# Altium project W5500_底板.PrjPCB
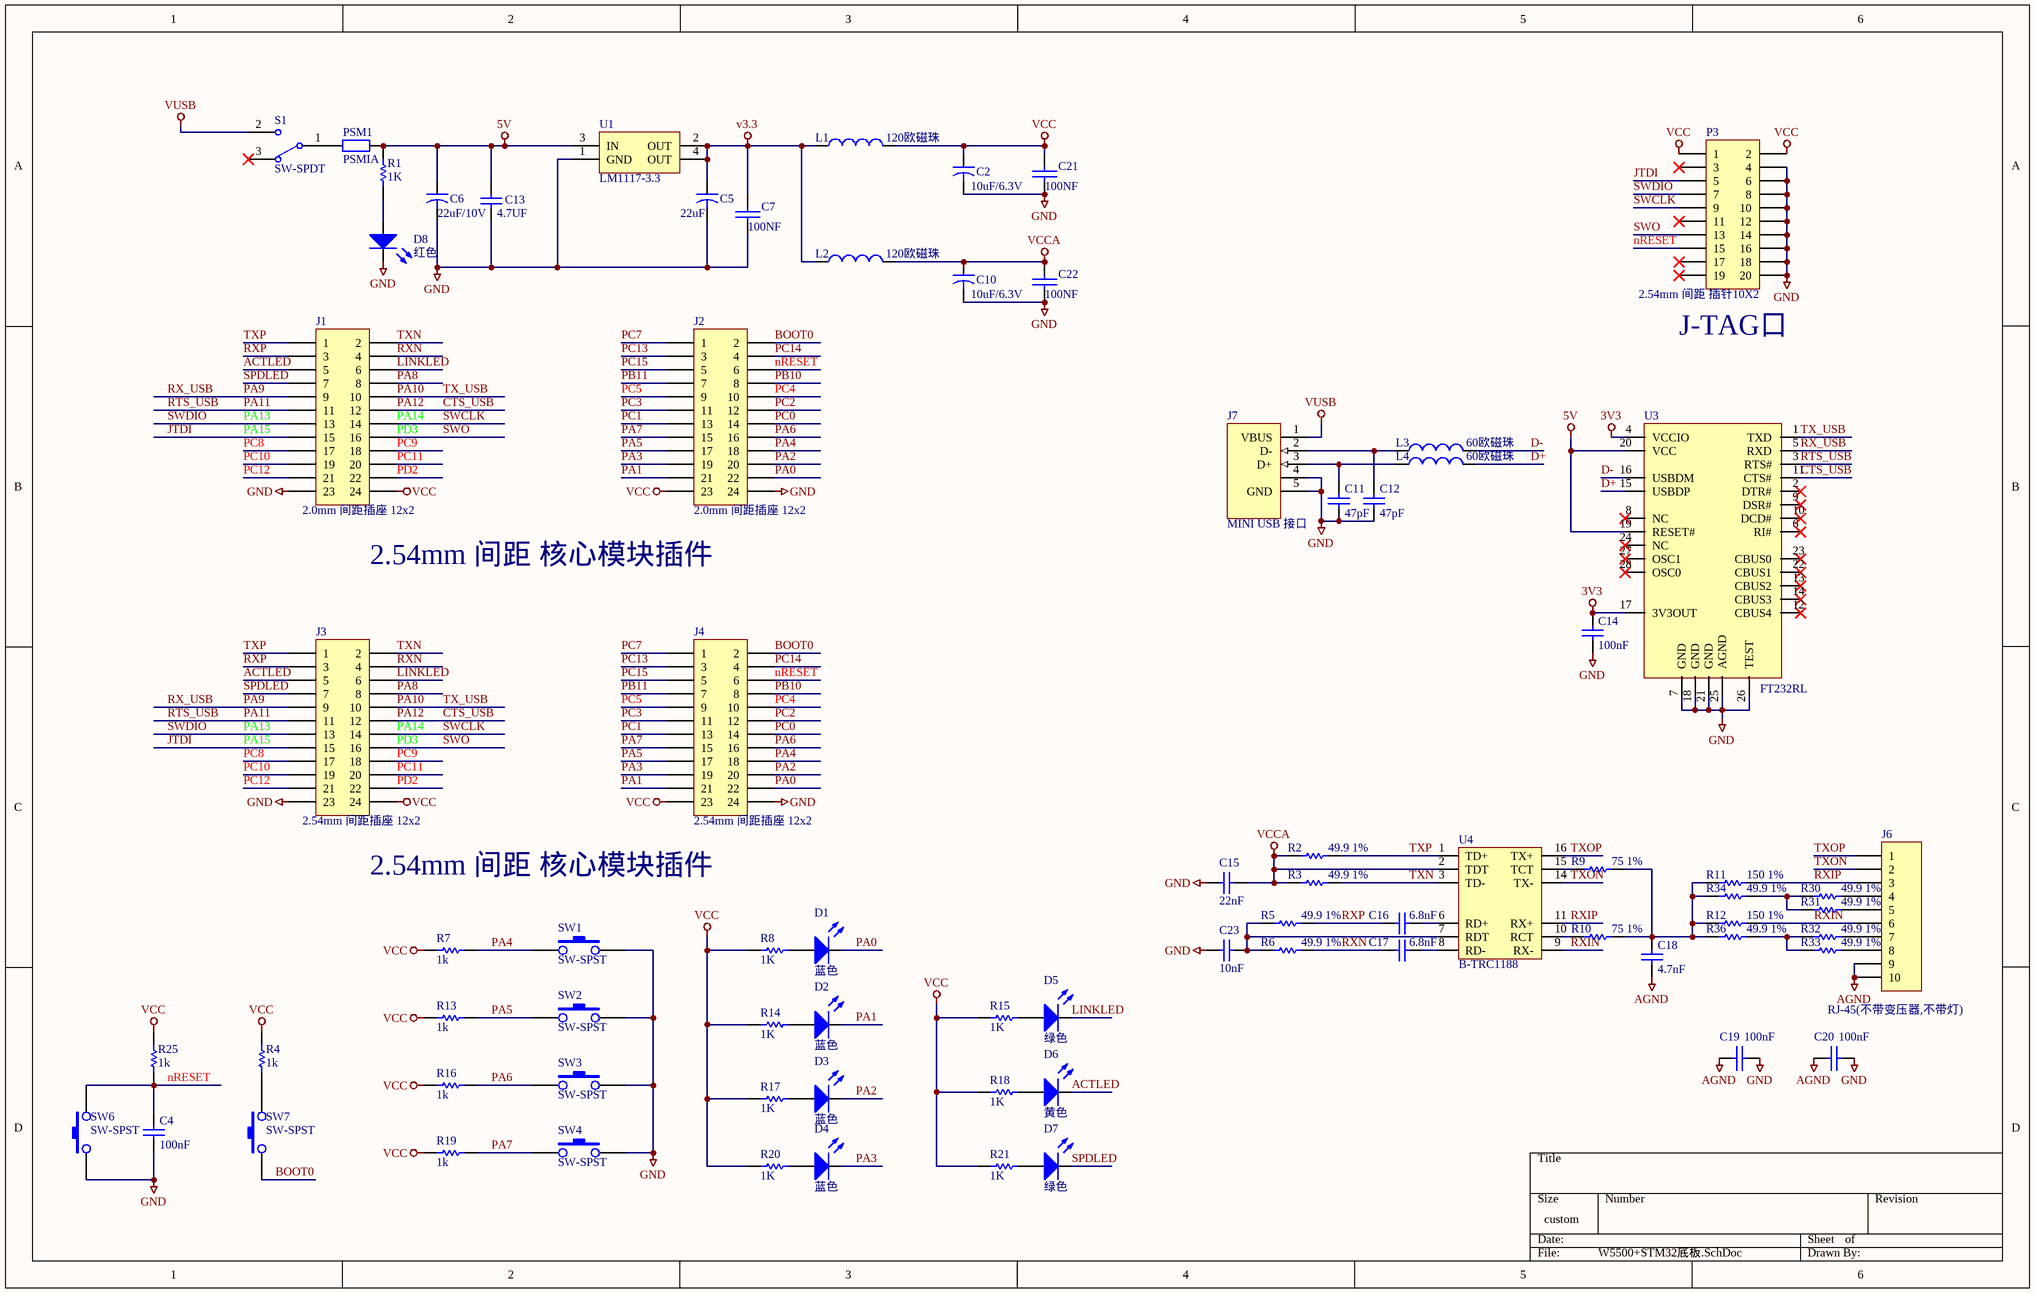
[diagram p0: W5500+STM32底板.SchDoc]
1 sheet, 77 parts. Net scope: global (net labels, ports and power ports of the same name join across sheets).
Board file: W5500_底板.PcbDoc

## Sheet W5500+STM32底板.SchDoc
size 381 x 241 mm

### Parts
C2  value 10uF/6.3V  [CR1206]  (hidden comment: Cap2)
C4  value 100nF  [CR0603]  (hidden comment: Cap)
C5  value 22uF  [CR1206]  (hidden comment: Cap2)
C6  value 22uF/10V  [cr1206]  (hidden comment: Cap2)
C7  value 100NF  [CR0603]  (hidden comment: 104)
C10  value 10uF/6.3V  [CR1206]  (hidden comment: Cap2)
C11  value 47pF  [CR0603]  (hidden comment: Cap)
C12  value 47pF  [CR0603]  (hidden comment: Cap)
C13  value 4.7UF  [CR0805]  (hidden comment: Cap)
C14  value 100nF  [CR0603]  (hidden comment: Cap)
C15  value 22nF  [CR0603]  (hidden comment: Cap)
C16  value 6.8nF  [CR0603]  (hidden comment: Cap)
C17  value 6.8nF  [CR0603]  (hidden comment: Cap)
C18  value 4.7nF  [CR0603]  (hidden comment: Cap)
C19  100nF  [CR0603]
C20  100nF  [CR0603]
C21  value 100NF  [CR0603]  (hidden comment: 104)
C22  value 100NF  [CR0603]  (hidden comment: 104)
C23  value 10nF  [CR0603]  (hidden comment: Cap)
D1  蓝色  [CR0603 发光二极管]
D2  蓝色  [CR0603 发光二极管]
D3  蓝色  [CR0603 发光二极管]
D4  蓝色  [CR0603 发光二极管]
D5  绿色  [CR0603 发光二极管]
D6  黄色  [CR0603 发光二极管]
D7  绿色  [CR0603 发光二极管]
D8  红色  [CR0603 发光二极管]
J1  2.0mm 间距插座 12x2  [HDR2X12]
J2  2.0mm 间距插座 12x2  [HDR2X12]
J3  2.54mm 间距插座 12x2  [HDR2X12]
J4  2.54mm 间距插座 12x2  [HDR2X12]
J6  RJ-45(不带变压器,不带灯)  [RJ-45(SC902-5921S)]
J7  MINI USB 接口  [440479]
L1  value 120欧磁珠  [cr0603]  (hidden comment: Inductor)
L2  value 120欧磁珠  [cr0603]  (hidden comment: Inductor)
L3  value 60欧磁珠  [cr0603]  (hidden comment: Inductor)
L4  value 60欧磁珠  [cr0603]  (hidden comment: Inductor)
P3  2.54mm 间距 插针10X2  [HDR2X10]
PSM1  PSMIA  [保险管？]
R1  value 1K  [CR0603]  (hidden comment: Res1)
R2  value 49.9 1%  [CR0603]  (hidden comment: Res1)
R3  value 49.9 1%  [CR0603]  (hidden comment: Res1)
R4  value 1k  [CR0603]  (hidden comment: Res1)
R5  value 49.9 1%  [CR0603]  (hidden comment: Res1)
R6  value 49.9 1%  [CR0603]  (hidden comment: Res1)
R7  value 1k  [CR0603]  (hidden comment: Res1)
R8  value 1K  [CR0603]  (hidden comment: Res1)
R9  value 75 1%  [CR0603]  (hidden comment: Res1)
R10  value 75 1%  [CR0603]  (hidden comment: Res1)
R11  value 150 1%  [CR0603]  (hidden comment: Res1)
R12  value 150 1%  [CR0603]  (hidden comment: Res1)
R13  value 1k  [CR0603]  (hidden comment: Res1)
R14  value 1K  [CR0603]  (hidden comment: Res1)
R15  value 1K  [CR0603]  (hidden comment: Res1)
R16  value 1k  [CR0603]  (hidden comment: Res1)
R17  value 1K  [CR0603]  (hidden comment: Res1)
R18  value 1K  [CR0603]  (hidden comment: Res1)
R19  value 1k  [CR0603]  (hidden comment: Res1)
R20  value 1K  [CR0603]  (hidden comment: Res1)
R21  value 1K  [CR0603]  (hidden comment: Res1)
R25  value 1k  [CR0603]  (hidden comment: Res1)
R30  value 49.9 1%  [CR0603]  (hidden comment: Res1)
R31  value 49.9 1%  [CR0603]  (hidden comment: Res1)
R32  value 49.9 1%  [CR0603]  (hidden comment: Res1)
R33  value 49.9 1%  [CR0603]  (hidden comment: Res1)
R34  value 49.9 1%  [CR0603]  (hidden comment: Res1)
R36  value 49.9 1%  [CR0603]  (hidden comment: Res1)
S1  SW-SPDT  [单刀双路拨码]
SW1  SW-SPST  [直插上位按键]
SW2  SW-SPST  [直插上位按键]
SW3  SW-SPST  [直插上位按键]
SW4  SW-SPST  [直插上位按键]
SW6  SW-SPST  [直插上位按键]
SW7  SW-SPST  [直插上位按键]
U1  LM1117-3.3  [SOT-223]
U3  FT232RL  [SSOP28]
U4  B-TRC1188  [11FB-05NL]

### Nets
3V3: C14.2 U3.4(VCCIO) U3.17(3V3OUT)
5V: C6.1 C13.2 PSM1.2 R1.1 U1.3(IN) U3.19(RESET#) U3.20(VCC)
AGND: C18.1 C19.1 C20.1 J6.9 J6.10
GND: C2.2 C4.1 C5.2 C6.2 C7.2 C10.2 C11.1 C12.1 C13.1 C14.1 C15.2 C19.2 C20.2 C21.2 C22.2 C23.1 D8.2(K) J1.23 J2.24 J3.23 J4.24 J7.4 J7.5(GND) J7.6(SHLD) J7.7(SHLD) J7.8(SHLD) J7.9(SHLD) P3.4 P3.6 P3.8 P3.10 P3.12 P3.14 P3.16 P3.18 P3.20 SW1.3 SW2.3 SW3.3 SW4.3 SW6.3 U1.1(GND) U3.7(GND) U3.18(GND) U3.21(GND) U3.25(AGND) U3.26(TEST)
v3.3: C5.1 C7.1 L1.1 L2.1 U1.2(OUT) U1.4(OUT)
VCC: C2.1 C21.1 J1.24 J2.23 J3.24 J4.23 L1.2 P3.1 P3.2 R4.1 R7.1 R8.1 R13.1 R14.1 R15.1 R16.1 R17.1 R18.1 R19.1 R20.1 R21.1 R25.1
VCCA: C10.1 C15.1 C22.1 L2.2 R2.2 R3.2 U4.2(TDT)
VUSB: J7.1(VBUS) S1.2
ACTLED: D6.2(K) J1.5 J3.5
BOOT0: J2.2 J4.2 SW7.3
CTS_USB: J1.12 J3.12 U3.11(CTS#)  [also labelled PA12]
D+: L4.2 U3.15(USBDP)
D-: L3.2 U3.16(USBDM)
JTDI: J1.15 J3.15 P3.5  [also labelled PA15]
LINKLED: D5.2(K) J1.6 J3.6
nRESET: C4.2 J2.6 J4.6 P3.15 R25.2 SW6.1
PA0: D1.2(K) J2.22 J4.22
PA1: D2.2(K) J2.21 J4.21
PA2: D3.2(K) J2.20 J4.20
PA3: D4.2(K) J2.19 J4.19
PA4: J2.18 J4.18 R7.2 SW1.1
PA5: J2.17 J4.17 R13.2 SW2.1
PA6: J2.16 J4.16 R16.2 SW3.1
PA7: J2.15 J4.15 R19.2 SW4.1
PA8: J1.8 J3.8
PA9: J1.9 J3.9 U3.5(RXD)  [also labelled RX_USB]
PA10: J1.10 J3.10 U3.1(TXD)  [also labelled TX_USB]
PA11: J1.11 J3.11 U3.3(RTS#)  [also labelled RTS_USB]
PA13: J1.13 J3.13 P3.7  [also labelled SWDIO]
PA14: J1.14 J3.14 P3.9  [also labelled SWCLK]
PB10: J2.8 J4.8
PB11: J2.7 J4.7
PC0: J2.14 J4.14
PC1: J2.13 J4.13
PC2: J2.12 J4.12
PC3: J2.11 J4.11
PC4: J2.10 J4.10
PC5: J2.9 J4.9
PC7: J2.1 J4.1
PC8: J1.17 J3.17
PC9: J1.18 J3.18
PC10: J1.19 J3.19
PC11: J1.20 J3.20
PC12: J1.21 J3.21
PC13: J2.3 J4.3
PC14: J2.4 J4.4
PC15: J2.5 J4.5
PD2: J1.22 J3.22
PD3: J1.16 J3.16 P3.13  [also labelled SWO]
RXIN: J6.6 R12.1 U4.9(RX-)
RXIP: J6.3 R11.1 U4.11(RX+)
RXN: C17.2 J1.4 J3.4 R6.1
RXP: C16.1 J1.3 J3.3 R5.1
SPDLED: D7.2(K) J1.7 J3.7
TXN: J1.2 J3.2 R3.1 U4.3(TD-)
TXON: J6.2 U4.14(TX-)
TXOP: J6.1 U4.16(TX+)
TXP: J1.1 J3.1 R2.1 U4.1(TD+)
NetC11_2: C11.2 J7.3(D+) L4.1
NetC12_2: C12.2 J7.2(D-) L3.1
NetC16_2: C16.2 U4.6(RD+)
NetC17_1: C17.1 U4.8(RD-)
NetC18_2: C18.2 R9.1 R10.1 R11.2 R12.2 R34.2 R36.2
NetC23_2: C23.2 R5.2 R6.2 U4.7(RDT)
NetD1_1: D1.1(A) R8.2
NetD2_1: D2.1(A) R14.2
NetD3_1: D3.1(A) R17.2
NetD4_1: D4.1(A) R20.2
NetD5_1: D5.1(A) R15.2
NetD6_1: D6.1(A) R18.2
NetD7_1: D7.1(A) R21.2
NetD8_1: D8.1(A) R1.2
NetJ6_4: J6.4 R30.1
NetJ6_5: J6.5 R31.1
NetJ6_7: J6.7 R32.1
NetJ6_8: J6.8 R33.1
NetPSM1_1: PSM1.1 S1.1
NetR4_2: R4.2 SW7.1
NetR9_2: R9.2 U4.15(TCT)
NetR10_2: R10.2 U4.10(RCT)
NetR30_2: R30.2 R31.2 R34.1
NetR32_2: R32.2 R33.2 R36.1

Not connected (* = marked no-connect by the designer): P3 3* 11* 17* 19*; S1 3*; U3 2(DTR#)* 6(RI#)* 8(NC)* 9(DSR#)* 10(DCD#)* 12(CBUS4)* 13(CBUS2)* 14(CBUS3)* 22(CBUS1)* 23(CBUS0)* 24(NC)* 27(OSC1)* 28(OSC0)*

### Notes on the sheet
- (near P3) J-TAG口
- (near J1) 2.54mm 间距 核心模块插件
- 2.54mm 间距 核心模块插件

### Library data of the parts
C2 C5 C6 C10 = Cap2: Capacitor
C4 C11-C18 C23 = Cap: Capacitor
C7 C19-C22 = CAP: Capacitor
D1-D8 = LED1: Typical RED GaAs LED
J1-J4 = Header 12X2: Header, 12-Pin, Dual row
J6 = Header 10: Header, 10-Pin
J7 = 440479-2: USB 2.0, Right Angle, SMT, AB Type, Receptacle, 5 Position, Black; ContactMaterial: Phosphor Bronze; ContactPlating: Gold (30) over Nickel; PCB_Layout: Complies with manufacturer's recommendation.; DrillSize: Corresponds to nominal value.; PanelGround: Without
L1-L4 = Inductor: Code_IEC: 1005
P3 = Header 10X2: Header, 10-Pin, Dual row
PSM1 = Res2: Resistor; Value: 1K
R1-R21 R25 R30-R34 R36 = Res1: Resistor
S1 = SW-SPDT: SPDT Subminiature Toggle Switch, Right Angle Mounting, Vertical Actuation
SW1-SW4 SW6 SW7 = SW-PB
U1 = REG1117-3.3: 800mA and 1A Low Dropout Positive Regulator 2.85V, 3.3V, 5V, and Adjustable; Package Information: Latest Revision: revC
U4 = 11FB-05NL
